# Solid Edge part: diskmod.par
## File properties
Author: Deepak Maini
Template: NORMENG.PAR
Last saved by: CADCIM
Revision: 5
Application: Solid Edge
Accuracy: 0.99
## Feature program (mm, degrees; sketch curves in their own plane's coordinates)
sketch for "unnamed Protrusion 1" plane through (0, 0, 0) normal (0, 0, 1) x-axis (1, 0, 0)
  line (-25.2008, 3.175) -> (-20.6375, 3.175)
  arc centre (-20.6375, 0) radius 3.175 from (-20.6375, 3.175) to (-20.6375, -3.175) cw
  line (-25.2008, -3.175) -> (-20.6375, -3.175)
  arc centre (0, 0) radius 25.4 from (-3.175, -25.2008) to (-25.2008, -3.175) cw
  line (-3.175, -25.2008) -> (-3.175, -20.6375)
  arc centre (0, -20.6375) radius 3.175 from (-3.175, -20.6375) to (3.175, -20.6375) cw
  line (3.175, -25.2008) -> (3.175, -20.6375)
  arc centre (0, 0) radius 25.4 from (25.2008, -3.175) to (3.175, -25.2008) cw
  line (25.2008, -3.175) -> (20.6375, -3.175)
  arc centre (20.6375, 0) radius 3.175 from (20.6375, -3.175) to (20.6375, 3.175) cw
  line (25.2008, 3.175) -> (20.6375, 3.175)
  arc centre (0, 0) radius 25.4 from (3.175, 25.2008) to (25.2008, 3.175) cw
  line (3.175, 25.2008) -> (3.175, 20.6375)
  arc centre (0, 20.6375) radius 3.175 from (3.175, 20.6375) to (-3.175, 20.6375) cw
  line (-3.175, 25.2008) -> (-3.175, 20.6375)
  arc centre (0, 0) radius 25.4 from (-25.2008, 3.175) to (-3.175, 25.2008) cw
extrude "unnamed Protrusion 1" add finite 3.175 along +normal
sketch for "Hole_1" plane through (0, 0, 3.175) normal (0, 0, 1) x-axis (1, 0, 0)
  hole centre (0, 0) bore radius 12.7
hole "Hole_1" diameter 25.4 through
sketch for "ExtrudedProtrusion_2" plane through (0, 0, 3.175) normal (0, 0, 1) x-axis (1, 0, 0)
extrude "ExtrudedProtrusion_2" add finite 15.875 along +normal
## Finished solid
Body 1: solid body, 22 faces, 52 edges, 32 vertices.
  Faces by surface: plane 12, cylinder 10
  Edges by curve: line 32, circle 20
Bounding box of the edges (mm): 50.402 x 50.402 x 19.050, from (-25.2008, -25.2008, 0) to (25.2008, 25.2008, 19.05).
Cylindrical faces by radius (mm): R3.175 x4, R12.7 x1, R15.3815 x1, R25.4 x4
Planar faces by outward normal: +x 2, +y 2, +z 2, -x 2, -y 2, -z 2
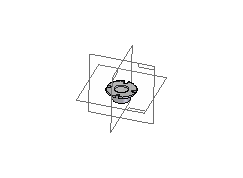
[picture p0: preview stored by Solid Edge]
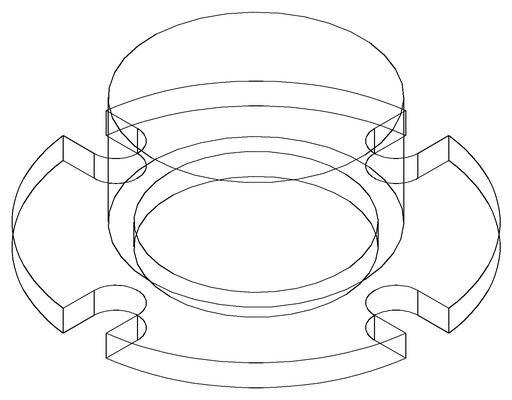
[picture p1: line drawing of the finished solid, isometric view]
